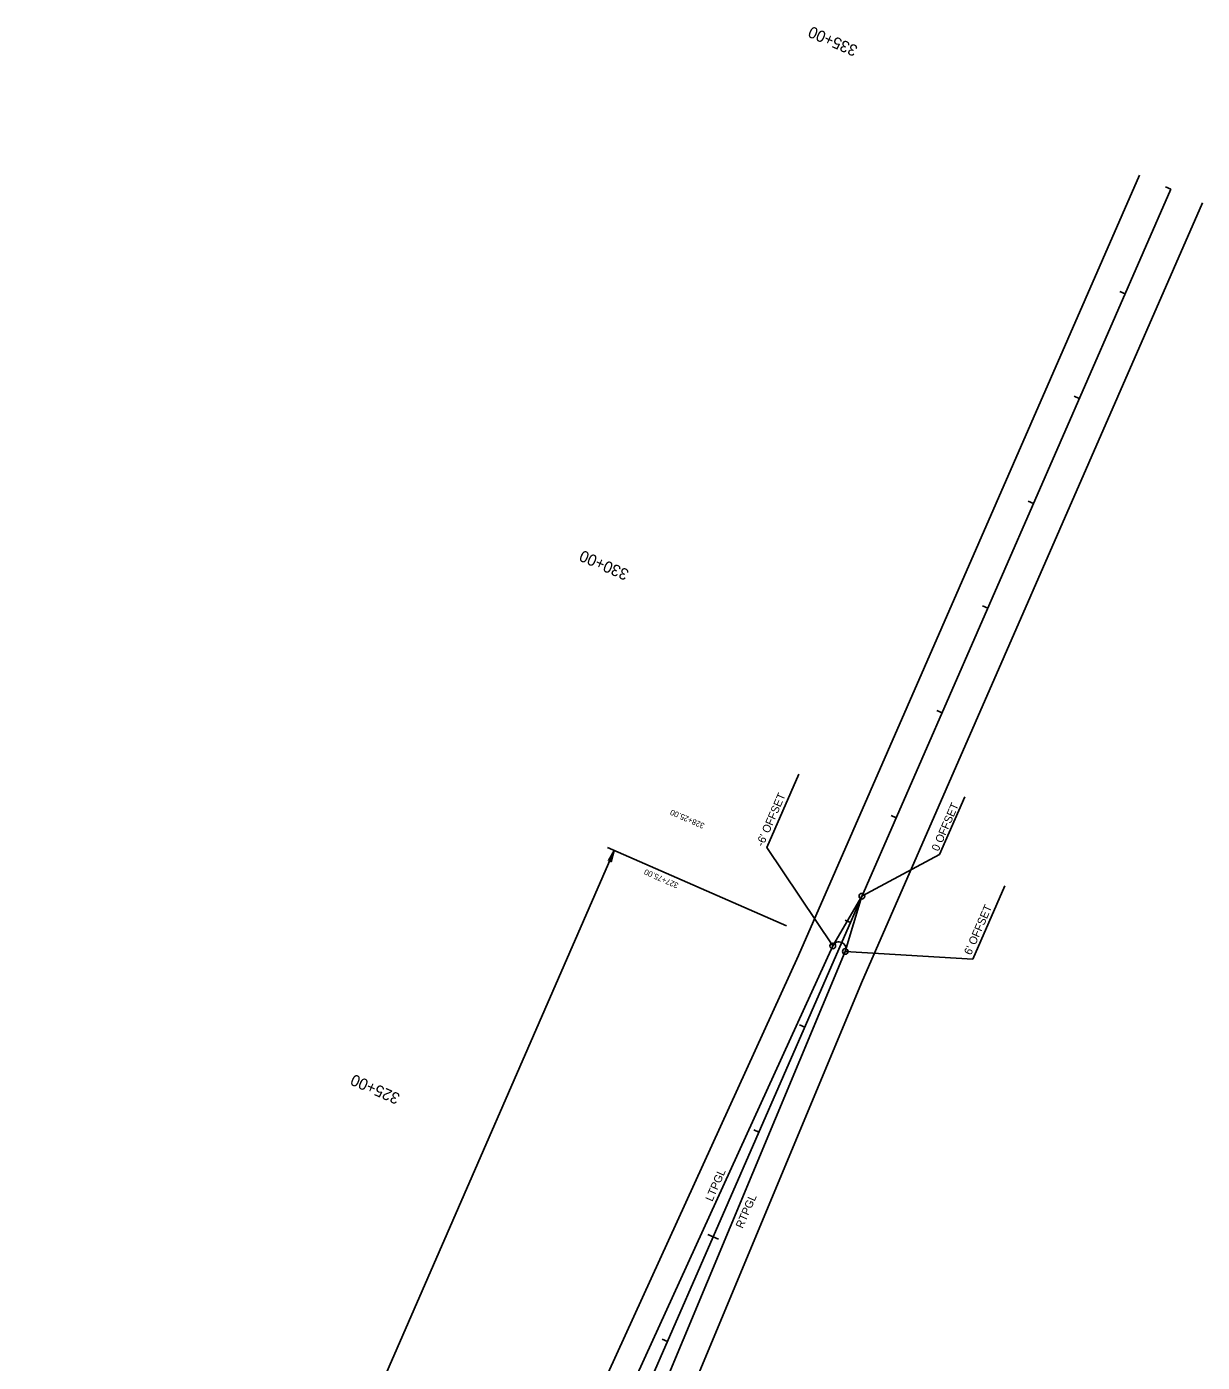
# Model space of a CAD drawing. Extents: x 2457443 to 2458788, y 602018 to 604471.
# Drawn here: x 2457760 to 2458788, y 603303 to 604471 of the extents above; entities that cross this region are included whole.
import ezdxf

# ---------------------------------------------------------------- set-up
doc = ezdxf.new("R2010")
doc.units = 0
for name, color, linetype in [('DESIGN - CENTERLINE - Proposed', 7, 'Continuous'), ('DESIGN - CENTERLINE - Proposed Curve Text', 7, 'Continuous'), ('DESIGN - CENTERLINE - Proposed Text', 7, 'Continuous'), ('DESIGN - TRANSPORTATION - Edge of Traveled Way', 7, 'Continuous'), ('DESIGN - TRANSPORTATION - Text', 7, 'Continuous')]:
    doc.layers.add(name, color=color, linetype=linetype)

msp = doc.modelspace()

# ---------------------------------------------------------------- linework, layer by layer
at = {"layer": 'DESIGN - CENTERLINE - Proposed'}
msp.add_line((2457759.6, 602037.7), (2458760.1, 604328.7), dxfattribs=at)
at = {"layer": 'DESIGN - CENTERLINE - Proposed Text'}
for p, q in [((2458760.1, 604328.7), (2458755.5, 604330.7)), ((2458720, 604237.1), (2458715.5, 604239.1)), ((2458680, 604145.5), (2458675.4, 604147.5)), ((2458640, 604053.8), (2458635.4, 604055.8)), ((2458600, 603962.2), (2458595.4, 603964.2)), ((2458560, 603870.5), (2458555.4, 603872.5)), ((2458520, 603778.9), (2458515.4, 603780.9)), ((2458479.9, 603687.2), (2458475.3, 603689.2)), ((2458439.9, 603595.6), (2458435.3, 603597.6)), ((2458399.9, 603504), (2458395.3, 603506)), ((2458359.9, 603412.3), (2458355.3, 603414.3)), ((2458364.5, 603410.3), (2458359.9, 603412.3)), ((2458319.9, 603320.7), (2458315.3, 603322.7))]:
    msp.add_line(p, q, dxfattribs=at)
at = {"layer": 'DESIGN - TRANSPORTATION - Edge of Traveled Way'}
for p, q in [((2458434.6, 603658.4), (2458732.6, 604340.7)), ((2458489.6, 603634.4), (2458787.6, 604316.7)), ((2457985.9, 602675.8), (2458434.6, 603658.4)), ((2458073.9, 602637.4), (2458489.6, 603634.4))]:
    msp.add_line(p, q, dxfattribs=at)
for points in [[(2458007.7, 602665.9), (2458464.4, 603666.7), (2458489.9, 603710.2)], [(2458051.7, 602646.6), (2458475.4, 603661.9), (2458489.9, 603710.2)]]:
    msp.add_lwpolyline(points, dxfattribs=at)
msp.add_arc((2458469.9, 603664.3), 6, 336.4105, 156.4105, dxfattribs=at)
at = {"layer": 'DESIGN - TRANSPORTATION - Text'}
for p, q in [((2457833.2, 602742.1), (2458273.4, 603750.1)), ((2458423.9, 603684.4), (2458267.5, 603752.7))]:
    msp.add_line(p, q, dxfattribs=at)
for points in [[(2458464.4, 603666.7), (2458406.7, 603752.8), (2458434.7, 603817)], [(2458489.9, 603710.2), (2458557.8, 603746.7), (2458579.8, 603797)], [(2458273.4, 603750.1), (2458268.3, 603741.4), (2458269.9, 603742.1), (2458270.6, 603740.4), (2458273.4, 603750.1)], [(2458475.4, 603661.9), (2458586.8, 603655.2), (2458614.8, 603719.3)]]:
    msp.add_lwpolyline(points, dxfattribs=at)
msp.add_lwpolyline([(2458273.4, 603750.1), (2458268.3, 603741.4), (2458269.9, 603742.1), (2458270.6, 603740.4)], close=True, dxfattribs=at)
for centre in [(2458489.9, 603710.2), (2458464.4, 603666.7), (2458475.4, 603661.9)]:
    msp.add_circle(centre, 2.5, dxfattribs=at)

# ---------------------------------------------------------------- texts
at = {"layer": 'DESIGN - CENTERLINE - Proposed Curve Text'}
for s, p in [('328+25.00', (2458352.8, 603773.6)), ('327+75.00', (2458330, 603721.4))]:
    msp.add_text(s, height=5, rotation=156.4105, dxfattribs=at).set_placement(p)
at = {"layer": 'DESIGN - CENTERLINE - Proposed Text'}
for s, p in [('335+00', (2458487.1, 604453.4)), ('330+00', (2458287, 603995.2)), ('325+00', (2458086.9, 603536.9))]:
    msp.add_text(s, height=10, rotation=156.4105, dxfattribs=at).set_placement(p)
at = {"layer": 'DESIGN - TRANSPORTATION - Text'}
for s, p in [("-6' OFFSET", (2458403.5, 603753.1)), ('0 OFFSET', (2458556.9, 603749)), ("6' OFFSET", (2458585.3, 603658.2)), ('LTPGL', (2458359.1, 603442.7)), ('RTPGL', (2458385.6, 603419.1))]:
    msp.add_text(s, height=7, rotation=66.4105, dxfattribs=at).set_placement(p)

doc.saveas('drawing.dxf')
